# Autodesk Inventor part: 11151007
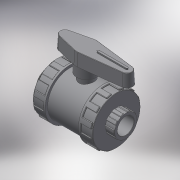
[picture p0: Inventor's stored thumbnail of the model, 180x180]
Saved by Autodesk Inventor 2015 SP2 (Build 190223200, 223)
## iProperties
Created: 2017-11
Part Number: 11151007
Material: Generic
Description: 2/NUT VALVE FEMALE THREAD 3/4" PVC
Document SubType Name: Modeling
Designer: KIM
Density: 1 g/cm^3
Appearance: Default
Author: KIM
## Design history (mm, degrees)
derived "111510.ipt"
feature "Solid1::111510.ipt"
tag "TaggingFeature1"
body "Solid1"
other parameters: "d0" = 89, "d1" = 24.117, "d2" = 55, "d3" = 16, "d4" = 19.2936, "d5" = 11.2, "d7" = 33.7638, "d8" = 49.5, "d13" = 0.72351, "d23" = 16, "d24" = 52.8, "d25" = 0.48234, "d26" = 0.72351, "d27" = 8.25, "d28" = 4.125, "d29" = 12, "d30" = 0, "d35" = 0.72351, "d39" = 27.5, "d45" = 360 deg, "d47" = 0.48234, "d50" = 30.25, "d51" = 16.5, "d53" = 0, "d55" = 4.8234, "d56" = 2.4117, "d57" = 11.2, "d58" = 0, "d59" = 0.72351, "d61" = 360 deg, "d63" = 22, "d64" = 54, "d66" = 73, "d68" = 11, "d69" = 21.9, "d70" = 13.5, "d71" = 3 deg, "d73" = 1.1, "d74" = 29.2, "d75" = 1.62, "d76" = 0, "d77" = 0.48234, "G_" = 24.117, "l_" = 16, "H_" = 89, "K_" = 55, "F_" = 54, "J_" = 73, "d67" = 22, "d72" = 5.5
